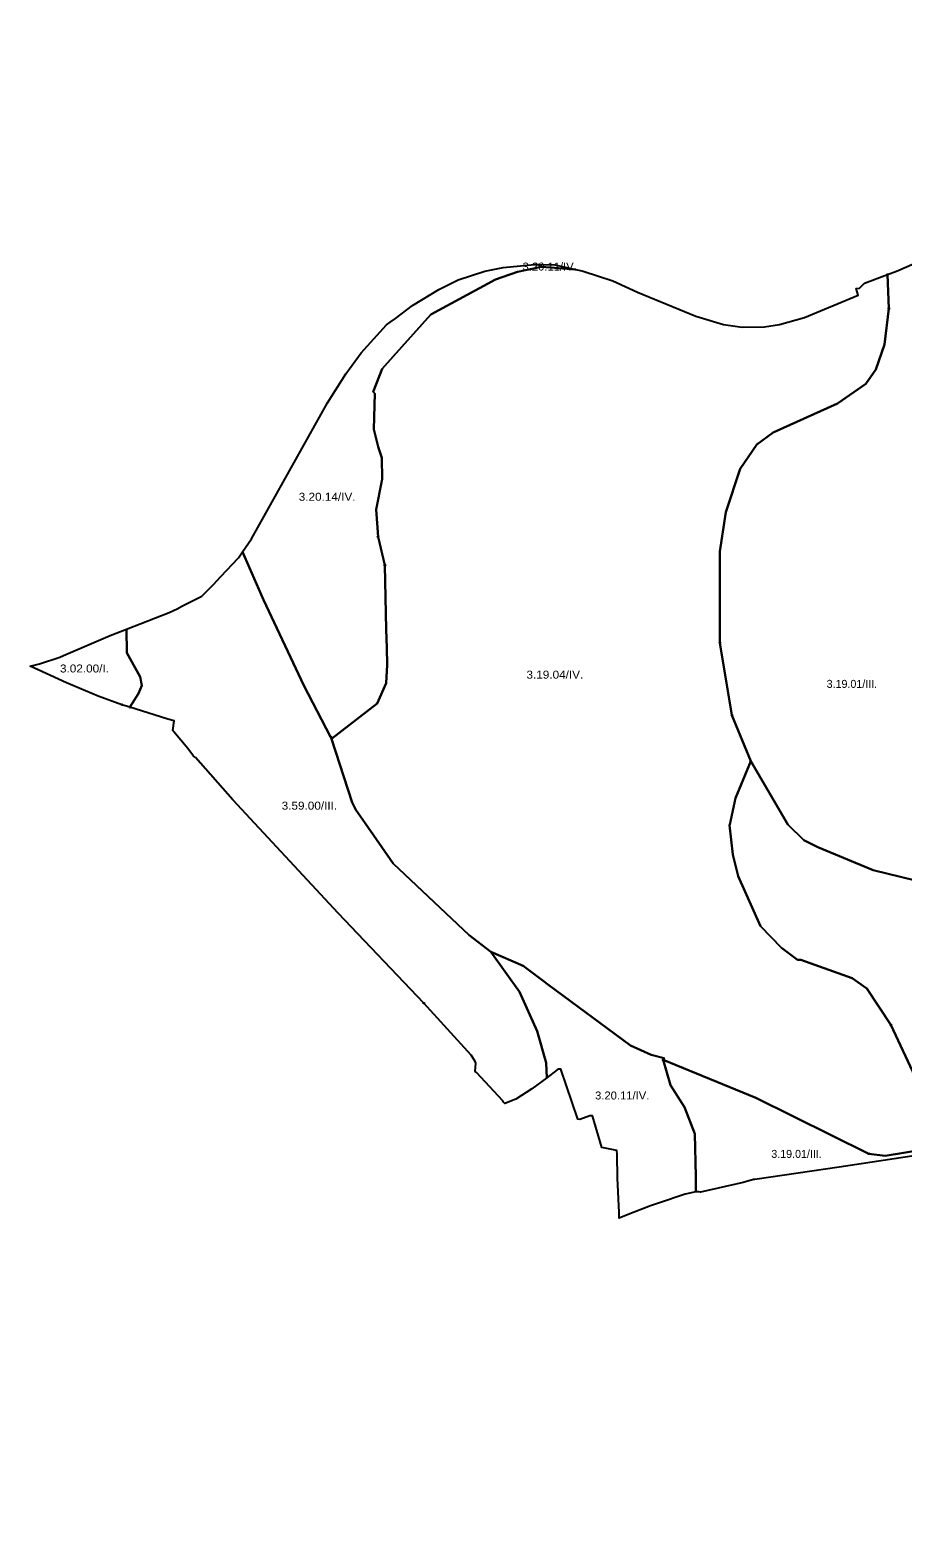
# Model space of a CAD drawing. Extents: x -650455 to -642254, y -1075222 to -1066610.
# Drawn here: x -650455 to -649362, y -1070894 to -1069005 of the extents above; entities that cross this region are included whole.
import ezdxf
from ezdxf.enums import TextEntityAlignment as Align

# ---------------------------------------------------------------- set-up
doc = ezdxf.new("R2010")
doc.units = 0
doc.header["$LTSCALE"] = 4
doc.header["$PDMODE"] = 32
doc.header["$PDSIZE"] = 2
for name, color, linetype, lineweight in [('1', 7, 'Continuous', 25), ('11', 7, 'Continuous', 13), ('13', 7, 'Continuous', 13), ('14', 7, 'Continuous', 13)]:
    doc.layers.add(name, color=color, linetype=linetype, lineweight=lineweight)
doc.layers.add('2', color=7, linetype='Continuous')

msp = doc.modelspace()

# ---------------------------------------------------------------- linework, layer by layer
at = {"layer": '1'}
for points in [[(-649346, -1070070.001), (-649399, -1070057), (-649468.5, -1070028.5), (-649486, -1070019.5), (-649506, -1070000), (-649552.5, -1069920.501), (-649576, -1069863), (-649591, -1069772.5), (-649591, -1069658.001), (-649583.5, -1069608.501), (-649565.5, -1069554.5), (-649545, -1069524.001), (-649524.5, -1069509), (-649444, -1069472.501), (-649408.5, -1069448.001), (-649396, -1069430), (-649385, -1069398.501), (-649379.5, -1069353.501), (-649381.394, -1069310.889), (-649369.938, -1069306.536), (-649315.968, -1069283.372)], [(-649872, -1069317.001), (-649844.5, -1069307.5), (-649814.5, -1069301.501), (-649771.549, -1069304.733)], [(-649771.549, -1069304.733), (-649762.294, -1069306.879), (-649724.928, -1069318.909), (-649694.004, -1069333.086), (-649620.99, -1069363.16), (-649586.63, -1069373.471), (-649563.008, -1069376.908), (-649535.232, -1069376.567), (-649516.622, -1069373.471), (-649485.269, -1069364.878), (-649418.056, -1069336.61), (-649420.58, -1069328.309), (-649416.046, -1069328.038), (-649410.126, -1069321.807), (-649381.394, -1069310.889), (-649379.5, -1069353.501), (-649385, -1069398.501), (-649396, -1069430), (-649408.5, -1069448.001), (-649444, -1069472.501), (-649524.5, -1069509), (-649545, -1069524.001), (-649565.5, -1069554.5), (-649583.5, -1069608.501), (-649591, -1069658.001), (-649591, -1069772.5), (-649576, -1069863), (-649552.5, -1069920.501), (-649571.5, -1069967), (-649578.779, -1070000), (-649579, -1070001.001), (-649575, -1070037.501), (-649568, -1070064.5), (-649540, -1070127.501), (-649514, -1070154.5), (-649494, -1070169.5), (-649489.5, -1070169.5), (-649425.5, -1070192.501), (-649407, -1070205.5), (-649377, -1070251)], [(-649292.5, -1070400), (-649384, -1070415.001), (-649404.5, -1070412.5), (-649546, -1070342.501), (-649662, -1070295), (-649661, -1070292.501), (-649677, -1070288.501), (-649703, -1070277.001), (-649807, -1070200.001), (-649812.5, -1070196.001), (-649837.5, -1070177.001), (-649878, -1070159.501), (-649905, -1070138.5), (-650000, -1070048.642), (-650035, -1069998.501), (-650047, -1069981.501), (-650051.5, -1069972.5), (-650077.5, -1069892.501), (-650020, -1069848.501), (-650009, -1069823.001), (-650007.5, -1069800.001), (-650008, -1069778.501), (-650009, -1069755.501), (-650010.5, -1069675), (-650019, -1069639.5), (-650021.5, -1069605.501), (-650014, -1069567.5), (-650014.5, -1069540.501), (-650019, -1069527), (-650024.5, -1069504.501), (-650023, -1069460.001), (-650025, -1069458), (-650014, -1069429), (-650000, -1069413.588), (-649953, -1069361), (-649872, -1069317.001)], [(-650270.588, -1069729.643), (-650264.049, -1069725.946), (-650255.7, -1069721.679), (-650239.895, -1069713.738), (-650225.292, -1069699.561), (-650215.758, -1069689.37), (-650193.939, -1069666.049), (-650188.652, -1069658.257), (-650162.5, -1069718.501), (-650112, -1069826), (-650078.5, -1069890), (-650077.5, -1069892.501)], [(-650077.5, -1069892.501), (-650051.5, -1069972.5), (-650047, -1069981.501), (-650035, -1069998.501), (-650000, -1070048.642), (-649905, -1070138.5), (-649878, -1070159.501), (-649842, -1070209.5), (-649820, -1070259), (-649808.5, -1070298.5), (-649807.717, -1070317.164), (-649826.581, -1070331.184), (-649846.749, -1070344.254), (-649860.384, -1070349.654), (-649861.83, -1070347.66), (-649862.919, -1070346.16), (-649895.894, -1070310.722), (-649897.267, -1070309.246), (-649896.686, -1070299), (-649897.814, -1070295.897), (-649902.47, -1070288.984), (-649961.726, -1070223.802), (-650068.951, -1070110.933), (-650201.007, -1069969.002), (-650247.565, -1069916.095), (-650250.296, -1069914.295), (-650257.394, -1069904.811), (-650274.649, -1069883.815), (-650275.847, -1069882.316), (-650274.512, -1069869.914), (-650282.347, -1069867.929), (-650283.315, -1069867.653), (-650329.752, -1069853.025), (-650319, -1069836.001), (-650315, -1069826), (-650317, -1069815.001), (-650333.5, -1069785), (-650334.218, -1069755.215), (-650280.697, -1069734.361), (-650270.588, -1069729.643)], [(-649346.5, -1070316), (-649377, -1070251), (-649407, -1070205.5), (-649425.5, -1070192.501), (-649489.5, -1070169.5), (-649494, -1070169.5), (-649514, -1070154.5), (-649540, -1070127.501), (-649568, -1070064.5), (-649575, -1070037.501), (-649579, -1070001.001), (-649578.779, -1070000), (-649571.5, -1069967), (-649552.5, -1069920.501), (-649506, -1070000), (-649486, -1070019.5), (-649468.5, -1070028.5), (-649399, -1070057), (-649346, -1070070.001)], [(-649377, -1070251), (-649346.5, -1070316)]]:
    msp.add_lwpolyline(points, dxfattribs=at)
for points in [[(-649818.531, -1069298.366), (-649814.5, -1069301.501), (-649844.5, -1069307.5), (-649872, -1069317.001), (-649953, -1069361), (-650000, -1069413.588), (-650014, -1069429), (-650025, -1069458), (-650023, -1069460.001), (-650024.5, -1069504.501), (-650019, -1069527), (-650014.5, -1069540.501), (-650014, -1069567.5), (-650021.5, -1069605.501), (-650019, -1069639.5), (-650010.5, -1069675), (-650009, -1069755.501), (-650008, -1069778.501), (-650007.5, -1069800.001), (-650009, -1069823.001), (-650020, -1069848.501), (-650077.5, -1069892.501), (-650078.5, -1069890), (-650112, -1069826), (-650162.5, -1069718.501), (-650188.652, -1069658.257), (-650177.618, -1069641.99), (-650082.27, -1069471.857), (-650059.506, -1069435.338), (-650040.179, -1069409.131), (-650008.396, -1069373.9), (-650003.985, -1069370.65), (-649997.357, -1069365.862), (-649975.754, -1069349.841), (-649943.113, -1069329.649), (-649918.631, -1069317.62), (-649885.56, -1069306.879), (-649862.367, -1069302.152), (-649823.283, -1069298.286)], [(-649771.549, -1069304.733), (-649814.5, -1069301.501), (-649818.531, -1069298.366), (-649797.513, -1069298.715)], [(-650329.752, -1069853.025), (-650339.703, -1069849.89), (-650369.611, -1069838.983), (-650409.177, -1069822.466), (-650454.618, -1069801.419), (-650443.047, -1069798.805), (-650417.278, -1069790.212), (-650413.013, -1069788.371), (-650354.571, -1069763.146), (-650334.218, -1069755.215), (-650333.5, -1069785), (-650317, -1069815.001), (-650315, -1069826), (-650319, -1069836.001)], [(-649662, -1070295), (-649653, -1070326.501), (-649635.5, -1070354.001), (-649622.5, -1070387.501), (-649621, -1070441), (-649621.21, -1070460.1), (-649634.533, -1070463.237), (-649666.664, -1070474.064), (-649677.731, -1070477.753), (-649705.767, -1070488.481), (-649717.06, -1070493.18), (-649717.163, -1070485.927), (-649719.252, -1070442.915), (-649719.534, -1070413.56), (-649720.003, -1070408.189), (-649738.655, -1070404.538), (-649750.723, -1070364.872), (-649753.828, -1070365.153), (-649766.247, -1070369.387), (-649768.787, -1070369.106), (-649790.354, -1070306.655), (-649793.194, -1070306.371), (-649794.694, -1070307.486), (-649807.717, -1070317.164), (-649808.5, -1070298.5), (-649820, -1070259), (-649842, -1070209.5), (-649878, -1070159.501), (-649837.5, -1070177.001), (-649812.5, -1070196.001), (-649807, -1070200.001), (-649703, -1070277.001), (-649677, -1070288.501), (-649661, -1070292.501)], [(-649292.5, -1070400), (-649290.153, -1070406.417), (-649441.654, -1070429.367), (-649547.261, -1070444.531), (-649548.761, -1070444.745), (-649561.895, -1070448.418), (-649615.231, -1070460.576), (-649617.552, -1070460.168), (-649621.118, -1070460.078), (-649621.21, -1070460.1), (-649621, -1070441), (-649622.5, -1070387.501), (-649635.5, -1070354.001), (-649653, -1070326.501), (-649662, -1070295), (-649546, -1070342.501), (-649404.5, -1070412.5), (-649384, -1070415.001)]]:
    msp.add_lwpolyline(points, close=True, dxfattribs=at)
at = {"layer": '11'}
msp.add_line((-650339.703, -1069849.89), (-650329.752, -1069853.025), dxfattribs=at)
msp.add_lwpolyline([(-650329.752, -1069853.025), (-650319, -1069836.001), (-650315, -1069826), (-650317, -1069815.001), (-650333.5, -1069785), (-650334.218, -1069755.215), (-650354.571, -1069763.146), (-650413.013, -1069788.371), (-650417.278, -1069790.212), (-650443.047, -1069798.805), (-650454.618, -1069801.419), (-650409.177, -1069822.466), (-650369.611, -1069838.983), (-650339.703, -1069849.89)], dxfattribs=at)
for p in [(-650339.703, -1069849.89), (-650329.752, -1069853.025)]:
    msp.add_point(p, dxfattribs=at)
at = {"layer": '13'}
for points in [[(-648964.5, -1068859.501), (-648977.155, -1068829.971), (-648978.256, -1068830.599), (-649260.164, -1069077.084), (-649288.704, -1069124.951), (-649290.507, -1069162.185), (-649295.587, -1069197.042), (-649300.809, -1069224.704), (-649315.697, -1069282.325), (-649315.968, -1069283.372), (-649369.938, -1069306.536), (-649381.394, -1069310.889), (-649379.5, -1069353.501)], [(-649379.5, -1069353.501), (-649385, -1069398.501), (-649396, -1069430), (-649408.5, -1069448.001), (-649444, -1069472.501), (-649524.5, -1069509), (-649545, -1069524.001), (-649565.5, -1069554.5), (-649583.5, -1069608.501), (-649591, -1069658.001), (-649591, -1069772.5), (-649576, -1069863), (-649552.5, -1069920.501)], [(-649961.726, -1070223.802), (-649902.47, -1070288.984), (-649897.814, -1070295.897), (-649896.686, -1070299), (-649897.267, -1070309.246), (-649895.894, -1070310.722), (-649862.919, -1070346.16), (-649861.83, -1070347.66), (-649860.384, -1070349.654), (-649846.749, -1070344.254), (-649826.581, -1070331.184), (-649807.717, -1070317.164), (-649808.5, -1070298.5), (-649820, -1070259), (-649842, -1070209.5), (-649878, -1070159.501), (-649905, -1070138.5), (-650000, -1070048.642), (-650035, -1069998.501), (-650047, -1069981.501), (-650051.5, -1069972.5), (-650077.5, -1069892.501), (-650078.5, -1069890), (-650112, -1069826), (-650162.5, -1069718.501), (-650188.652, -1069658.257), (-650193.939, -1069666.049), (-650215.758, -1069689.37), (-650225.292, -1069699.561), (-650239.895, -1069713.738), (-650255.7, -1069721.679), (-650264.049, -1069725.946), (-650270.588, -1069729.643), (-650280.697, -1069734.361), (-650334.218, -1069755.215), (-650333.5, -1069785), (-650317, -1069815.001), (-650315, -1069826), (-650319, -1069836.001), (-650329.752, -1069853.025)], [(-650329.752, -1069853.025), (-650283.315, -1069867.653), (-650282.347, -1069867.929), (-650274.512, -1069869.914), (-650275.847, -1069882.316), (-650274.649, -1069883.815), (-650257.394, -1069904.811), (-650250.296, -1069914.295), (-650247.565, -1069916.095), (-650201.007, -1069969.002), (-650068.951, -1070110.933), (-649961.726, -1070223.802)], [(-649552.5, -1069920.501), (-649506, -1070000), (-649486, -1070019.5), (-649468.5, -1070028.5)], [(-649468.5, -1070028.5), (-649399, -1070057), (-649346, -1070070.001)]]:
    msp.add_lwpolyline(points, dxfattribs=at)
msp.add_lwpolyline([(-649621, -1070441), (-649621.21, -1070460.1), (-649621.118, -1070460.078), (-649617.552, -1070460.168), (-649615.231, -1070460.576), (-649561.895, -1070448.418), (-649548.761, -1070444.745), (-649547.261, -1070444.531), (-649441.654, -1070429.367), (-649290.153, -1070406.417), (-649292.5, -1070400), (-649384, -1070415.001), (-649404.5, -1070412.5), (-649546, -1070342.501), (-649662, -1070295), (-649653, -1070326.501), (-649635.5, -1070354.001), (-649622.5, -1070387.501)], close=True, dxfattribs=at)
for p in [(-649379.5, -1069353.501), (-649552.5, -1069920.501), (-649961.726, -1070223.802)]:
    msp.add_point(p, dxfattribs=at)
at = {"layer": '14'}
msp.add_line((-649576, -1069863), (-649591, -1069772.5), dxfattribs=at)
for points in [[(-650019, -1069639.5), (-650021.5, -1069605.501), (-650014, -1069567.5), (-650014.5, -1069540.501), (-650019, -1069527), (-650024.5, -1069504.501), (-650023, -1069460.001), (-650025, -1069458), (-650014, -1069429), (-650000, -1069413.588), (-649953, -1069361), (-649872, -1069317.001), (-649844.5, -1069307.5), (-649814.5, -1069301.501), (-649818.531, -1069298.366), (-649823.283, -1069298.286), (-649862.367, -1069302.152), (-649885.56, -1069306.879), (-649918.631, -1069317.62), (-649943.113, -1069329.649), (-649975.754, -1069349.841), (-649997.357, -1069365.862), (-650003.985, -1069370.65), (-650008.396, -1069373.9), (-650040.179, -1069409.131), (-650059.506, -1069435.338), (-650082.27, -1069471.857), (-650177.618, -1069641.99), (-650188.652, -1069658.257), (-650162.5, -1069718.501), (-650112, -1069826), (-650078.5, -1069890)], [(-649381.394, -1069310.889), (-649410.126, -1069321.807), (-649416.046, -1069328.038), (-649420.58, -1069328.309), (-649418.056, -1069336.61), (-649485.269, -1069364.878), (-649516.622, -1069373.471), (-649535.232, -1069376.567), (-649563.008, -1069376.908), (-649586.63, -1069373.471), (-649620.99, -1069363.16), (-649694.004, -1069333.086), (-649724.928, -1069318.909), (-649762.294, -1069306.879), (-649771.549, -1069304.733), (-649814.5, -1069301.501), (-649844.5, -1069307.5), (-649872, -1069317.001), (-649953, -1069361), (-650000, -1069413.588), (-650014, -1069429), (-650025, -1069458), (-650023, -1069460.001), (-650024.5, -1069504.501), (-650019, -1069527), (-650014.5, -1069540.501), (-650014, -1069567.5), (-650021.5, -1069605.501), (-650019, -1069639.5), (-650010.5, -1069675)], [(-649591, -1069772.5), (-649591, -1069658.001), (-649583.5, -1069608.501), (-649565.5, -1069554.5), (-649545, -1069524.001), (-649524.5, -1069509), (-649444, -1069472.501), (-649408.5, -1069448.001), (-649396, -1069430), (-649385, -1069398.501), (-649379.5, -1069353.501), (-649381.394, -1069310.889)], [(-650078.5, -1069890), (-650077.5, -1069892.501), (-650020, -1069848.501), (-650009, -1069823.001), (-650007.5, -1069800.001), (-650008, -1069778.501), (-650009, -1069755.501), (-650010.5, -1069675), (-650019, -1069639.5)], [(-650010.5, -1069675), (-650009, -1069755.501), (-650008, -1069778.501), (-650007.5, -1069800.001), (-650009, -1069823.001), (-650020, -1069848.501), (-650077.5, -1069892.501), (-650051.5, -1069972.5), (-650047, -1069981.501), (-650035, -1069998.501), (-650000, -1070048.642), (-649905, -1070138.5), (-649878, -1070159.501), (-649837.5, -1070177.001), (-649812.5, -1070196.001)], [(-649404.5, -1070412.5), (-649384, -1070415.001), (-649292.5, -1070400), (-649294.5, -1070394.001), (-649307, -1070368), (-649346.5, -1070316), (-649377, -1070251), (-649407, -1070205.5), (-649425.5, -1070192.501), (-649489.5, -1070169.5), (-649494, -1070169.5), (-649514, -1070154.5), (-649540, -1070127.501), (-649568, -1070064.5), (-649575, -1070037.501), (-649579, -1070001.001), (-649578.779, -1070000), (-649571.5, -1069967), (-649552.5, -1069920.501), (-649576, -1069863)], [(-649346, -1070070.001), (-649399, -1070057), (-649468.5, -1070028.5), (-649486, -1070019.5), (-649506, -1070000), (-649552.5, -1069920.501), (-649571.5, -1069967), (-649578.779, -1070000), (-649579, -1070001.001), (-649575, -1070037.501), (-649568, -1070064.5), (-649540, -1070127.501), (-649514, -1070154.5), (-649494, -1070169.5), (-649489.5, -1070169.5), (-649425.5, -1070192.501), (-649407, -1070205.5), (-649377, -1070251)], [(-649837.5, -1070177.001), (-649878, -1070159.501), (-649842, -1070209.5), (-649820, -1070259), (-649808.5, -1070298.5), (-649807.717, -1070317.164), (-649794.694, -1070307.486), (-649793.194, -1070306.371), (-649790.354, -1070306.655), (-649768.787, -1070369.106), (-649766.247, -1070369.387), (-649753.828, -1070365.153), (-649750.723, -1070364.872), (-649738.655, -1070404.538), (-649720.003, -1070408.189), (-649719.534, -1070413.56), (-649719.252, -1070442.915)], [(-649719.252, -1070442.915), (-649717.163, -1070485.927), (-649717.06, -1070493.18), (-649705.767, -1070488.481), (-649677.731, -1070477.753), (-649666.664, -1070474.064), (-649634.533, -1070463.237), (-649621.21, -1070460.1), (-649621, -1070441), (-649622.5, -1070387.501), (-649635.5, -1070354.001), (-649653, -1070326.501), (-649662, -1070295), (-649661, -1070292.501), (-649677, -1070288.501), (-649703, -1070277.001), (-649807, -1070200.001), (-649812.5, -1070196.001), (-649837.5, -1070177.001)], [(-649812.5, -1070196.001), (-649807, -1070200.001), (-649703, -1070277.001), (-649677, -1070288.501), (-649661, -1070292.501), (-649662, -1070295)], [(-649377, -1070251), (-649346.5, -1070316), (-649307, -1070368), (-649294.5, -1070394.001), (-649292.5, -1070400), (-649290.153, -1070406.417), (-649203.149, -1070393.237), (-649154.468, -1070385.26), (-649152.827, -1070384.991), (-649113.062, -1070507.22), (-649074.998, -1070628.551), (-649074.607, -1070630.05), (-649073.701, -1070633.531), (-649067.279, -1070658.191), (-649066.192, -1070662.363), (-649062.695, -1070674.37), (-649041.195, -1070748.176), (-649018.47, -1070821.77), (-648992.621, -1070893.659)], [(-649662, -1070295), (-649546, -1070342.501), (-649404.5, -1070412.5)]]:
    msp.add_lwpolyline(points, dxfattribs=at)
msp.add_lwpolyline([(-649771.549, -1069304.733), (-649797.513, -1069298.715), (-649818.531, -1069298.366), (-649814.5, -1069301.501)], close=True, dxfattribs=at)
for p in [(-649381.394, -1069310.889), (-650019, -1069639.5), (-650010.5, -1069675), (-649591, -1069772.5), (-649576, -1069863), (-650078.5, -1069890), (-649837.5, -1070177.001), (-649377, -1070251), (-649662, -1070295), (-649404.5, -1070412.5)]:
    msp.add_point(p, dxfattribs=at)

# ---------------------------------------------------------------- texts
at = {"layer": '2'}
for s, width, p in [('3.20.11/IV.', 1.05, (-649804.181, -1069305.953)), ('3.20.14/IV.', 1.1, (-650082.804, -1069594.355)), ('3.02.00/I.', 1.1, (-650386.633, -1069809.518)), ('3.19.04/IV.', 1.1, (-649797.663, -1069817.229)), ('3.59.00/III.', 1.1, (-650104.993, -1069981.368)), ('3.20.11/IV.', 1.05, (-649713.351, -1070344.46))]:
    msp.add_text(s, height=10, dxfattribs=dict(at, width=width)).set_placement(p, align=Align.CENTER)
for p in [(-649425.775, -1069828.792), (-649495.079, -1070417.623)]:
    msp.add_text('3.19.01/III.', height=10, dxfattribs=at).set_placement(p, align=Align.CENTER)

doc.saveas('drawing.dxf')
